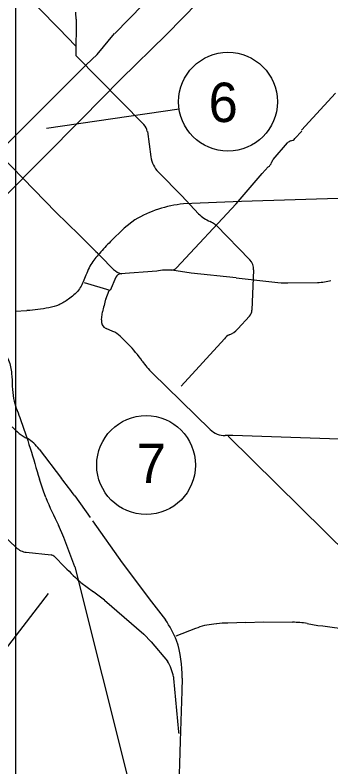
# Model space of a CAD drawing. Extents: x 105094 to 105814, y -291615 to -291123.
# Drawn here: x 105459.11 to 105478.52, y -291494.14 to -291448.01 of the extents above; entities that cross this region are included whole.
import ezdxf

# ---------------------------------------------------------------- set-up
doc = ezdxf.new("R2010")
doc.units = 0
doc.layers.add('G_BORDER', color=7, linetype='Continuous')
doc.layers.add('G_MAP', color=7, linetype='Continuous')

msp = doc.modelspace()

# ---------------------------------------------------------------- linework, layer by layer
at = {"layer": 'G_BORDER'}
for p, q in [((105459.139, -291158.398), (105459.139, -291578.398)), ((105461.043, -291454.953), (105469.189, -291453.762)), ((105461.154, -291483.504), (105455.794, -291490.435))]:
    msp.add_line(p, q, dxfattribs=at)
for centre in [(105472.193, -291453.323), (105467.166, -291475.618)]:
    msp.add_circle(centre, 3.035, dxfattribs=at)
at = {"layer": 'G_MAP'}
for p, q in [((105466.992, -291447.365), (105465.239, -291449.141)), ((105462.877, -291448.262), (105462.839, -291450.511)), ((105462.865, -291450.514), (105467.03, -291454.725)), ((105476.701, -291455.077), (105478.804, -291452.8)), ((105467.24, -291455.148), (105467.455, -291456.706)), ((105476.303, -291455.586), (105476.739, -291455.129)), ((105474.977, -291456.864), (105475.859, -291455.853)), ((105474.298, -291457.732), (105474.669, -291457.322)), ((105467.918, -291457.641), (105469.366, -291459.095)), ((105472.699, -291459.586), (105474.298, -291457.732)), ((105469.366, -291459.095), (105470.392, -291460.2)), ((105481.994, -291459.169), (105473.022, -291459.44)), ((105472.699, -291459.586), (105469.031, -291463.522)), ((105473.022, -291459.44), (105469.457, -291459.595)), ((105466.482, -291460.569), (105465.807, -291461.075)), ((105465.807, -291461.075), (105464.981, -291461.905)), ((105464.08, -291462.506), (105464.17, -291462.593)), ((105464.351, -291462.774), (105465.17, -291463.616)), ((105467.816, -291463.726), (105465.592, -291463.89)), ((105473.763, -291463.635), (105473.661, -291466.11)), ((105472.686, -291464.136), (105475.063, -291464.401)), ((105475.868, -291464.437), (105477.699, -291464.414)), ((105464.687, -291465.432), (105464.9, -291464.899)), ((105459.114, -291466.182), (105459.846, -291466.142)), ((105464.419, -291466.712), (105464.496, -291466.223)), ((105473.509, -291466.48), (105472.801, -291467.264)), ((105465.127, -291467.416), (105464.71, -291467.237)), ((105466.068, -291468.208), (105465.563, -291467.709)), ((105471.976, -291467.876), (105469.321, -291470.787)), ((105471.099, -291473.438), (105467.533, -291469.952)), ((105472.483, -291473.813), (105472.02, -291473.813)), ((105472.209, -291473.848), (105482.056, -291483.557)), ((105485.766, -291474.249), (105472.483, -291473.813)), ((105460.591, -291474.643), (105461.964, -291476.445)), ((105460.866, -291477.23), (105460.608, -291476.478)), ((105461.002, -291477.618), (105460.863, -291477.23)), ((105462.789, -291477.511), (105463.737, -291478.842)), ((105463.876, -291479.036), (105465.691, -291481.607)), ((105459.805, -291480.968), (105461.324, -291481.135)), ((105461.538, -291481.238), (105462.174, -291481.878)), ((105462.788, -291481.871), (105467.151, -291499.204)), ((105465.695, -291481.607), (105465.83, -291481.8)), ((105465.834, -291481.8), (105467.361, -291483.822)), ((105463.147, -291482.815), (105463.941, -291483.406)), ((105467.361, -291483.822), (105468.346, -291485.117)), ((105470.199, -291485.647), (105468.997, -291486.125)), ((105471.498, -291485.36), (105471.324, -291485.379)), ((105473.297, -291485.285), (105472.189, -291485.317)), ((105477.063, -291485.33), (105477.705, -291485.453)), ((105477.705, -291485.453), (105478.012, -291485.492)), ((105478.012, -291485.492), (105480.205, -291485.789)), ((105468.844, -291488.615), (105468.847, -291488.802)), ((105468.845, -291488.708), (105469.146, -291491.997)), ((105469.373, -291488.695), (105469.351, -291489.496)), ((105469.351, -291489.496), (105469.26, -291492.558)), ((105469.26, -291492.558), (105469.222, -291493.927)), ((105469.222, -291493.927), (105469.073, -291498.28))]:
    msp.add_line(p, q, dxfattribs=at)
for points in [[(105462.839, -291449.907), (105461.796, -291448.822), (105455.634, -291442.573), (105455.331, -291442.001)], [(105471.669, -291445.853), (105471.33, -291446.221), (105468.414, -291449.206), (105465.61, -291451.938), (105463.22, -291454.38), (105458.379, -291459.237), (105456.07, -291461.521)], [(105452.64, -291461.892), (105455.457, -291459.092), (105455.925, -291458.656), (105458.88, -291455.656), (105459.723, -291454.825), (105463.482, -291451.066), (105464.151, -291450.417), (105465.219, -291449.141)], [(105457.478, -291455.895), (105458.935, -291457.348), (105461.619, -291460.093), (105463.046, -291461.488), (105464.351, -291462.774)], [(105471.386, -291460.844), (105471.472, -291460.9), (105473.53, -291463.022)], [(105472.686, -291464.136), (105469.925, -291463.852), (105468.738, -291463.666)], [(105465.31, -291464.091), (105464.955, -291464.915), (105463.372, -291464.427)], [(105453.642, -291475.011), (105456.257, -291477.908), (105459.185, -291480.671)], [(105462.788, -291481.871), (105462.107, -291480.063), (105461.774, -291479.304)], [(105464.61, -291483.916), (105467.016, -291485.989), (105467.481, -291486.461), (105468.485, -291487.649)], [(105473.297, -291485.285), (105474.379, -291485.237), (105476.155, -291485.266)]]:
    msp.add_lwpolyline(points, dxfattribs=at)
for centre, radius, start, end in [((105463.665, -291447.84), 0.844, 179.539, 195.3759), ((105462.27, -291448.243), 0.608, 358.1912, 17.0876), ((105466.499, -291455.251), 0.747, 7.8921, 44.6979), ((105475.922, -291455.223), 0.526, 284.5967, 316.3444), ((105476.154, -291456.112), 0.393, 104.7363, 138.8813), ((105469.082, -291456.482), 1.643, 187.8517, 224.8841), ((105474.384, -291456.896), 0.513, 303.8449, 341.6963), ((105475.375, -291457.211), 0.528, 138.9425, 163.0402), ((105470.236, -291467.007), 7.453, 96.0039, 120.2485), ((105471.984, -291458.592), 2.263, 225.2871, 246.7526), ((105469.204, -291464.215), 4.015, 57.0793, 61.967), ((105473.075, -291470.217), 11.602, 134.2403, 139.1725), ((105472.934, -291463.6), 0.83, 357.5954, 44.1095), ((105468.625, -291463.068), 0.608, 280.6627, 311.767), ((105465.811, -291462.993), 0.894, 224.209, 260.6336), ((105465.616, -291464.222), 0.333, 94.2, 156.7652), ((105468.463, -291466.544), 2.891, 84.0218, 102.928), ((105475.637, -291460.534), 3.91, 261.5609, 273.3777), ((105477.582, -291460.919), 3.497, 271.9143, 285.5435), ((105471.787, -291467.56), 7.412, 163.3136, 169.6083), ((105473.071, -291466.084), 0.591, 317.9071, 357.484), ((105464.902, -291466.787), 0.489, 171.15, 246.7803), ((105464.573, -291468.709), 1.407, 45.3, 66.8107), ((105472.461, -291468.145), 0.554, 110.3293, 151.076), ((105471.799, -291466.359), 1.35, 290.355, 317.8903), ((105461.16, -291473.172), 6.98, 34.2713, 45.3262), ((105471.097, -291466.308), 5.098, 215.1377, 225.6354), ((105461.346, -291471.055), 3.279, 222.6382, 243.4121), ((105472.02, -291472.496), 1.317, 225.6582, 270.0019), ((105458.588, -291476.104), 2.479, 36.1212, 58.6527), ((105448.906, -291487.403), 17.047, 35.4687, 40.0009), ((105486.359, -291467.028), 27.479, 202.6664, 206.5334), ((105459.918, -291479.935), 1.039, 225.1268, 263.7244), ((105461.286, -291481.489), 0.356, 44.8096, 83.7579), ((105477.356, -291467.16), 21.145, 224.111, 228.0718), ((105452.178, -291499.511), 19.943, 51.4385, 53.8549), ((105463.116, -291488.819), 6.408, 22.4, 35.2913), ((105471.682, -291489.382), 4.019, 95.1156, 111.6629), ((105472.214, -291491.381), 6.064, 90.2384, 96.7775), ((105476.082, -291492.705), 7.44, 82.4244, 89.4355), ((105462.484, -291488.499), 6.892, 358.3695, 17.9329), ((105466.025, -291489.112), 2.862, 10.0032, 30.7334), ((105469.244, -291491.989), 0.0987, 184.4896, 242.8796)]:
    msp.add_arc(centre, radius, start, end, dxfattribs=at)
for points in [[(105452.074, -291461.522), (105452.139, -291462.56), (105452.363, -291463.474), (105453.095, -291464.208), (105455.567, -291465.415), (105455.997, -291465.645), (105456.439, -291466.049), (105456.706, -291466.439), (105458.129, -291468.348), (105458.72, -291469.189), (105458.903, -291470.005), (105459.03, -291471.542), (105459.405, -291472.708), (105460.608, -291476.478)], [(105464.296, -291462.631), (105463.769, -291463.314), (105463.384, -291464.18), (105463.008, -291464.889), (105462.4, -291465.436), (105461.815, -291465.788), (105461.192, -291465.967), (105459.846, -291466.142)]]:
    msp.add_spline(points, degree=3, dxfattribs=at)

# ---------------------------------------------------------------- texts
at = {"layer": 'G_BORDER'}
for s, p in [('6', (105471.003, -291454.572)), ('7', (105466.587, -291476.72))]:
    msp.add_text(s, height=2.416, dxfattribs=at).set_placement(p)

doc.saveas('drawing.dxf')
